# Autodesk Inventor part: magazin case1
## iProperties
Created: 2006-04
Part Number: magazin case1
Document SubType Name: Modeling
Designer: Калинин
Author: Калинин
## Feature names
1. Выдавливание1 [Extrusion]
2. Выдавливание2 [Extrusion]
3. Выдавливание3 [Extrusion]
4. Выдавливание4 [Extrusion]
5. Выдавливание12 [Extrusion]
6. Выдавливание13 [Extrusion]
7. Выдавливание14 [Extrusion]
8. Разделение1
9. Сопряжение1 [Fillet]
10. Сопряжение2 [Fillet]
11. Выдавливание15 [Extrusion]
12. Выдавливание16 [Extrusion]
13. Разделение2
14. Разделение3
15. Выдавливание17 [Extrusion]
16. Выдавливание18 [Extrusion]
17. Выдавливание19 [Extrusion]
18. Выдавливание20 [Extrusion]
19. Выдавливание21 [Extrusion]
20. Выдавливание22 [Extrusion]
21. Сопряжение3 [Fillet]
22. Сопряжение4 [Fillet]
23. Сопряжение5 [Fillet]
24. Вращение1 [Revolution]
25. Сопряжение7 [Fillet]
26. Выдавливание24 [Extrusion]
27. Разделение4
28. Сопряжение8 [Fillet]
29. Сопряжение9 [Fillet]
30. Выдавливание25 [Extrusion]
31. Выдавливание26 [Extrusion]
32. Выдавливание27 [Extrusion]
33. Выдавливание28 [Extrusion]
34. Выдавливание29 [Extrusion]
35. Выдавливание30 [Extrusion]
36. Сопряжение10 [Fillet]
37. Выдавливание31 [Extrusion]
38. Выдавливание32 [Extrusion]
39. Вращение2 [Revolution]
40. Разделение5
41. Вращение3 [Revolution]
42. Разделение6
43. Сопряжение11 [Fillet]
44. Сопряжение12 [Fillet]
